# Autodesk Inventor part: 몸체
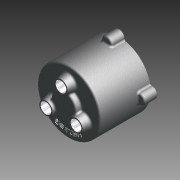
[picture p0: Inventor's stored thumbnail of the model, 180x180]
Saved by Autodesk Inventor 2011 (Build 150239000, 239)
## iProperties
Created: 2012-05
Part Number: 몸체
Document SubType Name: 모델링
Designer: SeoGD™
Material: 알루미늄-6061
Mass: 475.546 g
Surface Area: 687.663 cm^2
Volume: 175.478 cm^3
Density: 2.71 g/cm^3
변환 표준: STEP AP214IS
파일 이름: C:\Users\SeoGD\Desktop\?쒗뿕\紐몄껜.stp
전처리기: Build: 253, Release: 2010 SP1 - Date: Wed 07/29/2009
전송 단위: 밀리미터
불확실성: 0.01
Author: SeoGD™
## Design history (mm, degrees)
sketch "스케치2"
  geometry: C1 r 50 at (0, 0); 1 further point
  constraints: 1 centre point, 1 coincident
  dimensions: "d9" = 100 diameter of C1
extrude "돌출2" new body sketch "스케치2" distance "d10" = 80; taper "d11" = 0 deg
feature "쉘1" dims "d12" = 5
sketch "스케치3" dims "d13" = 55
  geometry: C1 r 7.5 at (0, 27.5); C2 r 12.5 at (0, 27.5); 2 further points
  constraints: 2 centre point, 2 coincident, 2 vertical alignment, 2 other
  dimensions: "d14" = 15 diameter of C1; "d15" = 25 diameter of C2
extrude "돌출3" join sketch "스케치3" distance "d16" = 12; taper "d17" = -10 deg
hole "구멍2" diameter "d20" = 15; stored, may be unused: countersink angle "d24" = 90 deg, drill point angle "d26" = 118 deg; dims "d18" = 10, "d19" = 10, "d21" = 6, "d22" = 4, "d23" = 2, "d25" = 15
chamfer "모따기1" distance "d27" = 1; stored, may be unused: second distance "d28" = 2, angle "d29" = 45 deg
sketch "스케치4"
  geometry: L1 (0, 0)-(0, 88); L2 (0, 70)-(13.16, 70); L3 (-45, 75)-(45, 75) reference; L4 (-50, 80)-(50, 80) reference; L5 (13.16, 70)-(14.5, 75); L6 (20, 80)-(20, 88); L7 (20, 88)-(0, 88); L8 (20, 80)-(14.5, 75)
  constraints: 12 end point, 3 point on line, 2 perpendicular, 1 vertical
  dimensions: "d34" = 40 diameter of L6 L1; "d35" = 105 deg angle of L5 L3; "d36" = 5 distance between parallel lines of L2 L3; "d37" = 8 distance between parallel lines of L7 L4; "d51" = 29 diameter of L5.end L1
revolve "회전1" sketch "스케치4" stored, may be unused: angle "d38" = 90 deg
hole "구멍3" diameter "d41" = 15; stored, may be unused: countersink angle "d45" = 90 deg, drill point angle "d47" = 0 deg; dims "d39" = 10, "d40" = 10, "d42" = 6, "d43" = 22, "d44" = 13, "d46" = 15
chamfer "모따기2" distance "d48" = 1; stored, may be unused: second distance "d49" = 2, angle "d50" = 45 deg
fillet "모깎기1" dims "d52" = 3
fillet "모깎기2" dims "d53" = 3, "d72" = 0.2
sketch "스케치5"
  geometry: A1 r 50 centre (0, 0) between (50, 0) and (-8.074, 49.344) reference; A2 r 8.5 centre (0, 52) between (8.074, 49.344) and (-8.074, 49.344); 1 further point
  constraints: 5 point on circle, 1 centre point, 1 horizontal alignment
  dimensions: "d54" = 90 deg dimension on point (0, 0) A2.centre A1.start; "d55" = 52 distance of A2.centre point (0, 0); "d56" = 17 diameter of A2
extrude "돌출4" join sketch "스케치5" distance "d57" = 20; taper "d58" = 0 deg
fillet "모깎기3" dims "d59" = 3
hole "구멍4" diameter "d62" = 4.134; stored, may be unused: countersink angle "d66" = 90 deg, drill point angle "d68" = 118 deg; dims "d60" = 10, "d61" = 10, "d63" = 12, "d64" = 22, "d65" = 13, "d67" = 15
sketch "스케치6"
  geometry: C1 r 47 at (0, 0) reference; C2 r 42.5 at (0, 0); 1 further point
  constraints: 1 centre point, 1 coincident, 1 other
  dimensions: "d73" = 85 diameter of C2
feature "엠보싱1" sketch "스케치6" dims "d74" = 1, "d75" = 0
node "솔리드1"
node "솔리드 본체"
node "곡면 본체"
pattern_circular "원형 패턴1" dims "d31" = 360 deg
pattern_circular "원형 패턴2" dims "d70" = 360 deg
node "솔리드2"
